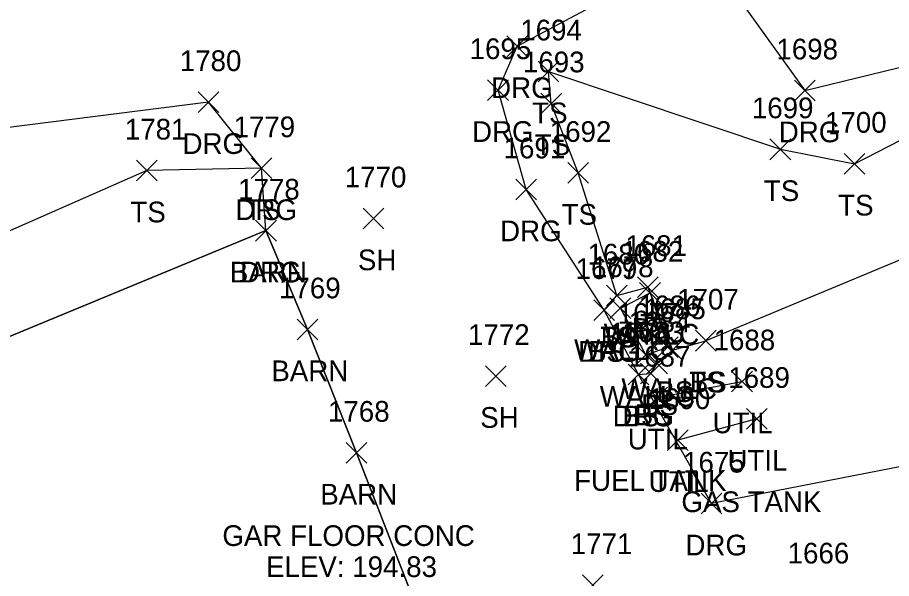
# Model space of a CAD drawing. Extents: x 1443590 to 1445966, y 578314 to 580556.
# Drawn here: x 1445041 to 1445125.4, y 578975.6 to 579029.8 of the extents above; entities that cross this region are included whole.
import ezdxf

# ---------------------------------------------------------------- set-up
doc = ezdxf.new("R2010")
doc.units = 0
for name, color, linetype in [('L_A', 7, 'Continuous'), ('L_C', 7, 'Continuous'), ('L_I', 7, 'Continuous'), ('L_TIC', 7, 'Continuous'), ('LBC', 7, 'Continuous'), ('LELB', 7, 'Continuous'), ('LSOGP', 7, 'Continuous'), ('LW', 7, 'Continuous'), ('R_A', 7, 'Continuous'), ('R_I', 7, 'Continuous'), ('R_TIC', 7, 'Continuous'), ('RDG', 7, 'Continuous'), ('U_A', 7, 'Continuous'), ('U_C', 7, 'Continuous'), ('U_I', 7, 'Continuous'), ('UDEFAULT', 7, 'Continuous')]:
    doc.layers.add(name, color=color, linetype=linetype)

msp = doc.modelspace()

# ---------------------------------------------------------------- linework, layer by layer
at = {"layer": 'L_TIC'}
for points in [[(1445091.274, 579023.588), (1445093.274, 579025.588)], [(1445093.274, 579023.588), (1445091.274, 579025.588)], [(1445091.534, 579020.505), (1445093.534, 579022.505)], [(1445093.534, 579020.505), (1445091.534, 579022.505)], [(1445113.642, 579016.07), (1445115.642, 579018.07)], [(1445115.642, 579016.07), (1445113.642, 579018.07)], [(1445120.814, 579014.675), (1445122.814, 579016.675)], [(1445122.814, 579014.675), (1445120.814, 579016.675)], [(1445052.487, 579014.014), (1445054.487, 579016.014)], [(1445054.487, 579014.014), (1445052.487, 579016.014)], [(1445063.555, 579014.237), (1445065.555, 579016.237)], [(1445065.555, 579014.237), (1445063.555, 579016.237)], [(1445094.12, 579013.786), (1445096.12, 579015.786)], [(1445096.12, 579013.786), (1445094.12, 579015.786)], [(1445074.369, 579009.393), (1445076.369, 579011.393)], [(1445076.369, 579009.393), (1445074.369, 579011.393)], [(1445063.988, 579008.214), (1445065.988, 579010.214)], [(1445065.988, 579008.214), (1445063.988, 579010.214)], [(1445100.851, 579002.769), (1445102.851, 579004.769)], [(1445102.851, 579002.769), (1445100.851, 579004.769)], [(1445101.061, 579002.215), (1445103.061, 579004.215)], [(1445103.061, 579002.215), (1445101.061, 579004.215)], [(1445097.853, 579001.943), (1445099.853, 579003.943)], [(1445099.853, 579001.943), (1445097.853, 579003.943)], [(1445097.853, 579001.943), (1445099.853, 579003.943)], [(1445099.853, 579001.943), (1445097.853, 579003.943)], [(1445096.626, 579000.545), (1445098.626, 579002.545)], [(1445098.626, 579000.545), (1445096.626, 579002.545)], [(1445098.197, 579000.718), (1445100.197, 579002.718)], [(1445100.197, 579000.718), (1445098.197, 579002.718)], [(1445067.992, 578998.677), (1445069.992, 579000.677)], [(1445069.992, 578998.677), (1445067.992, 579000.677)], [(1445102.766, 578996.947), (1445104.766, 578998.947)], [(1445104.766, 578996.947), (1445102.766, 578998.947)], [(1445102.766, 578996.947), (1445104.766, 578998.947)], [(1445104.766, 578996.947), (1445102.766, 578998.947)], [(1445106.45, 578997.588), (1445108.45, 578999.588)], [(1445108.45, 578997.588), (1445106.45, 578999.588)], [(1445106.45, 578997.588), (1445108.45, 578999.588)], [(1445108.45, 578997.588), (1445106.45, 578999.588)], [(1445100.672, 578996.217), (1445102.672, 578998.217)], [(1445102.672, 578996.217), (1445100.672, 578998.217)], [(1445100.672, 578996.217), (1445102.672, 578998.217)], [(1445102.672, 578996.217), (1445100.672, 578998.217)], [(1445103.232, 578996.667), (1445105.232, 578998.667)], [(1445105.232, 578996.667), (1445103.232, 578998.667)], [(1445103.232, 578996.667), (1445105.232, 578998.667)], [(1445105.232, 578996.667), (1445103.232, 578998.667)], [(1445101.751, 578995.396), (1445103.751, 578997.396)], [(1445103.751, 578995.396), (1445101.751, 578997.396)], [(1445101.134, 578994.425), (1445103.134, 578996.425)], [(1445103.134, 578994.425), (1445101.134, 578996.425)], [(1445086.183, 578994.173), (1445088.183, 578996.173)], [(1445088.183, 578994.173), (1445086.183, 578996.173)], [(1445099.961, 578994.313), (1445101.961, 578996.313)], [(1445101.961, 578994.313), (1445099.961, 578996.313)], [(1445072.714, 578986.76), (1445074.714, 578988.76)], [(1445074.714, 578986.76), (1445072.714, 578988.76)], [(1445095.533, 578973.969), (1445097.533, 578975.969)], [(1445097.533, 578973.969), (1445095.533, 578975.969)]]:
    msp.add_lwpolyline(points, dxfattribs=at)
at = {"layer": 'LBC'}
msp.add_lwpolyline([(1445114.369, 578870.765), (1445136.536, 578879.151), (1445166.742, 578891.137), (1445164.161, 578899.962), (1445158.757, 578912.889), (1445152.661, 578929.137), (1445146.858, 578942.986), (1445144.863, 578947.514), (1445143.987, 578947.248), (1445133.055, 578943.537), (1445109.106, 578933.86), (1445099.996, 578930.432), (1445096.669, 578929.401), (1445090.318, 578945.679), (1445084.319, 578960.519), (1445073.714, 578987.76), (1445068.992, 578999.677), (1445064.988, 579009.214), (1445035.364, 578996.981), (1445032.275, 578995.789)], dxfattribs=at)
at = {"layer": 'LELB'}
for points in [[(1445098.853, 579002.943), (1445095.12, 579014.786), (1445092.534, 579021.505), (1445092.274, 579024.588), (1445114.642, 579017.07), (1445121.814, 579015.675), (1445141.752, 579025.943), (1445149.606, 579014.31), (1445129.229, 579007.648), (1445107.45, 578998.588)], [(1445064.555, 579015.237), (1445053.487, 579015.014), (1445036.5, 579007.545), (1445035.364, 578996.981)], [(1445097.626, 579001.545), (1445098.853, 579002.943), (1445101.851, 579003.769), (1445104.232, 578997.667), (1445107.45, 578998.588)], [(1445100.961, 578995.313), (1445102.134, 578995.425), (1445102.751, 578996.396), (1445104.232, 578997.667)]]:
    msp.add_lwpolyline(points, dxfattribs=at)
at = {"layer": 'LSOGP'}
msp.add_lwpolyline([(1444912.11, 579017.324), (1444927.774, 579020.524), (1444932.596, 579021.372), (1444937.792, 579024.428), (1444942.73, 579026.633), (1444978.045, 579038.148), (1444989.096, 579041.73), (1445003.774, 579046.833), (1445011.665, 579023.729), (1445011.8, 579022.985), (1445000.151, 579018.401), (1445000.607, 579017.027), (1445005.008, 579004.527), (1445005.016, 579003.367), (1445011.648, 578983.968), (1445019.64, 578988.328), (1445029.432, 578994.289), (1445032.271, 578995.786), (1445035.368, 578996.983), (1445064.989, 579009.214), (1445068.989, 578999.674), (1445073.711, 578987.756), (1445084.319, 578960.519)], dxfattribs=at)
at = {"layer": 'LW'}
for points in [[(1445101.672, 578997.217), (1445099.197, 579001.718), (1445102.061, 579003.215), (1445103.766, 578997.947)], [(1445101.672, 578997.217), (1445103.766, 578997.947)]]:
    msp.add_lwpolyline(points, dxfattribs=at)
at = {"layer": 'R_TIC'}
for points in [[(1445088.236, 579026.017), (1445090.236, 579028.017)], [(1445090.236, 579026.017), (1445088.236, 579028.017)], [(1445086.387, 579021.783), (1445088.387, 579023.783)], [(1445088.387, 579021.783), (1445086.387, 579023.783)], [(1445116.003, 579021.752), (1445118.003, 579023.752)], [(1445118.003, 579021.752), (1445116.003, 579023.752)], [(1445058.444, 579020.625), (1445060.444, 579022.625)], [(1445060.444, 579020.625), (1445058.444, 579022.625)], [(1445063.555, 579014.237), (1445065.555, 579016.237)], [(1445065.555, 579014.237), (1445063.555, 579016.237)], [(1445089.098, 579012.192), (1445091.098, 579014.192)], [(1445091.098, 579012.192), (1445089.098, 579014.192)], [(1445063.988, 579008.214), (1445065.988, 579010.214)], [(1445065.988, 579008.214), (1445063.988, 579010.214)], [(1445096.626, 579000.545), (1445098.626, 579002.545)], [(1445098.626, 579000.545), (1445096.626, 579002.545)], [(1445099.961, 578994.313), (1445101.961, 578996.313)], [(1445101.961, 578994.313), (1445099.961, 578996.313)], [(1445106.991, 578981.848), (1445108.991, 578983.848)], [(1445108.991, 578981.848), (1445106.991, 578983.848)]]:
    msp.add_lwpolyline(points, dxfattribs=at)
at = {"layer": 'RDG'}
for points in [[(1445171.414, 579000.64), (1445169.072, 578997.459), (1445155.132, 578994.357), (1445131.623, 578987.461), (1445107.991, 578982.848), (1445100.961, 578995.313), (1445097.626, 579001.545), (1445090.098, 579013.192), (1445087.387, 579022.783), (1445089.236, 579027.017), (1445107.095, 579036.555), (1445117.003, 579022.752), (1445139.729, 579028.287), (1445135.538, 579040.733), (1445138.093, 579044.085), (1445140.88, 579046.598), (1445142.404, 579047.99)], [(1445064.988, 579009.214), (1445064.555, 579015.237), (1445059.444, 579021.625), (1445037.575, 579018.869), (1445021.054, 579010.784), (1445018.161, 579007.955)]]:
    msp.add_lwpolyline(points, dxfattribs=at)
at = {"layer": 'UDEFAULT'}
for points in [[(1445109.939, 578993.648), (1445111.939, 578995.648)], [(1445111.939, 578993.648), (1445109.939, 578995.648)], [(1445101.745, 578992.084), (1445103.745, 578994.084)], [(1445103.745, 578992.084), (1445101.745, 578994.084)], [(1445102.745, 578993.084), (1445110.939, 578994.648)], [(1445111.365, 578990.029), (1445113.365, 578992.029)], [(1445113.365, 578990.029), (1445111.365, 578992.029)], [(1445112.365, 578991.029), (1445104.755, 578988.981)], [(1445103.755, 578987.981), (1445105.755, 578989.981)], [(1445105.755, 578987.981), (1445103.755, 578989.981)]]:
    msp.add_lwpolyline(points, dxfattribs=at)

# ---------------------------------------------------------------- texts
at = {"layer": 'L_A'}
for s, p in [('TS', (1445090.684, 579019.588)), ('TS', (1445090.943, 579016.505)), ('TS', (1445113.052, 579012.07)), ('TS', (1445120.223, 579010.675)), ('TS', (1445051.897, 579010.014)), ('TS', (1445062.965, 579010.237)), ('TS', (1445093.529, 579009.786)), ('SH', (1445073.858, 579005.393)), ('BARN', (1445061.5, 579004.214)), ('BS', (1445100.291, 578998.769)), ('TS', (1445097.263, 578997.943)), ('BS', (1445097.294, 578997.943)), ('WALLC', (1445097.596, 578998.215)), ('WALLC', (1445094.733, 578996.718)), ('BS', (1445096.067, 578996.545)), ('BARN', (1445065.504, 578994.677)), ('TS', (1445105.859, 578993.588)), ('BS', (1445105.891, 578993.588)), ('WALLC', (1445099.302, 578992.947)), ('WALLC', (1445099.302, 578992.947)), ('BS', (1445102.673, 578992.667)), ('BS', (1445102.673, 578992.667)), ('WALLC', (1445097.207, 578992.217)), ('WALLC', (1445097.207, 578992.217)), ('BS', (1445101.192, 578991.396)), ('SH', (1445085.671, 578990.173)), ('BS', (1445099.402, 578990.313)), ('BS', (1445100.575, 578990.425)), ('BARN', (1445070.226, 578982.76))]:
    msp.add_text(s, height=2, dxfattribs=at).set_placement(p)
at = {"layer": 'L_C'}
for s, p in [('GAR FLOOR CONC', (1445060.777, 578978.76)), ('ELEV: 194.83', (1445064.99, 578975.76))]:
    msp.add_text(s, height=2, dxfattribs=at).set_placement(p)
at = {"layer": 'L_I'}
for s, p in [('1694', (1445089.534, 579027.588)), ('1693', (1445089.794, 579024.505)), ('1699', (1445111.894, 579020.07)), ('1781', (1445051.361, 579018.014)), ('1779', (1445061.855, 579018.237)), ('1700', (1445118.956, 579018.675)), ('1692', (1445092.38, 579017.786)), ('1770', (1445072.59, 579013.393)), ('1778', (1445062.295, 579012.214)), ('1682', (1445099.321, 579006.215)), ('1681', (1445099.677, 579006.769)), ('1680', (1445096.027, 579005.943)), ('1680', (1445096.027, 579005.943)), ('1679', (1445094.879, 579004.545)), ('1678', (1445096.457, 579004.718)), ('1769', (1445066.245, 579002.677)), ('1707', (1445104.678, 579001.588)), ('1707', (1445104.678, 579001.588)), ('1686', (1445100.971, 579000.947)), ('1686', (1445100.971, 579000.947)), ('1685', (1445101.492, 579000.667)), ('1685', (1445101.492, 579000.667)), ('1677', (1445098.932, 579000.217)), ('1677', (1445098.932, 579000.217)), ('1684', (1445100.011, 578999.396)), ('1772', (1445084.491, 578998.173)), ('1676', (1445098.166, 578998.313)), ('1683', (1445099.394, 578998.425)), ('1768', (1445070.974, 578990.76)), ('1771', (1445094.407, 578977.969)), ('1666', (1445115.347, 578977.068))]:
    msp.add_text(s, height=2, dxfattribs=at).set_placement(p)
at = {"layer": 'R_A'}
for p in [(1445086.724, 579022.017), (1445084.875, 579017.783), (1445114.491, 579017.752), (1445056.932, 579016.625), (1445062.043, 579010.237), (1445087.586, 579008.192), (1445062.476, 579004.214), (1445095.115, 578996.545), (1445098.449, 578990.313), (1445105.479, 578977.848)]:
    msp.add_text('DRG', height=2, dxfattribs=at).set_placement(p)
at = {"layer": 'R_I'}
for s, p in [('1695', (1445084.647, 579025.783)), ('1698', (1445114.263, 579025.752)), ('1780', (1445056.665, 579024.625)), ('1779', (1445061.855, 579018.237)), ('1691', (1445087.925, 579016.192)), ('1778', (1445062.295, 579012.214)), ('1679', (1445094.879, 579004.545)), ('1676', (1445098.166, 578998.313)), ('1675', (1445105.251, 578985.848))]:
    msp.add_text(s, height=2, dxfattribs=at).set_placement(p)
at = {"layer": 'U_A'}
for p in [(1445108.104, 578989.648), (1445099.911, 578988.084), (1445109.53, 578986.029), (1445101.92, 578983.981)]:
    msp.add_text('UTIL', height=2, dxfattribs=at).set_placement(p)
at = {"layer": 'U_C'}
for s, p in [('FUEL TANK', (1445094.73, 578984.084)), ('GAS TANK', (1445105.089, 578982.029))]:
    msp.add_text(s, height=2, dxfattribs=at).set_placement(p)
at = {"layer": 'U_I'}
for s, p in [('1688', (1445108.199, 578997.648)), ('1687', (1445100.005, 578996.084)), ('1689', (1445109.617, 578994.029)), ('1690', (1445101.928, 578991.981))]:
    msp.add_text(s, height=2, dxfattribs=at).set_placement(p)

doc.saveas('drawing.dxf')
